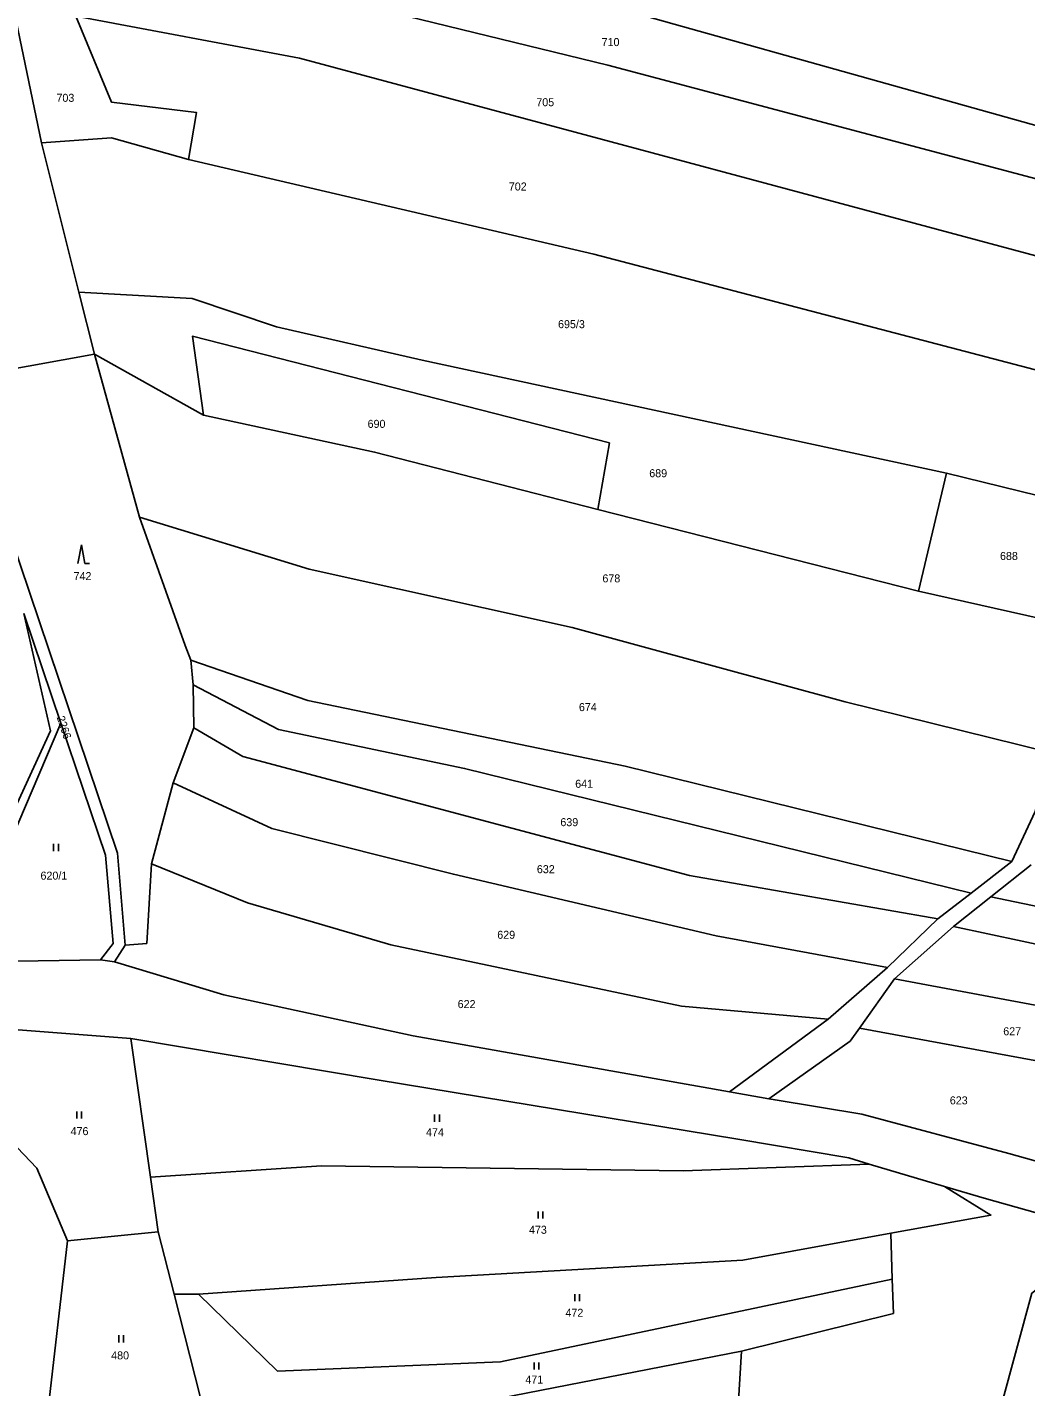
# Model space of a CAD drawing. Extents: x -725728 to -720881, y -1068679 to -1063504.
# Drawn here: x -722501.3 to -722289.2, y -1064708.2 to -1064419.4 of the extents above; entities that cross this region are included whole.
import ezdxf

# ---------------------------------------------------------------- set-up
doc = ezdxf.new("R2010")
doc.units = 0
for name, color, linetype in [('Hranice parcel', 7, 'Continuous'), ('Parcelní čísla', 7, 'Continuous'), ('Značky kultur', 7, 'Continuous')]:
    doc.layers.add(name, color=color, linetype=linetype)

# ---------------------------------------------------------------- blocks, each defined once
blk = doc.blocks.new('3.06_2')
at = {"layer": 'Značky kultur'}
for p, q in [((-0.051, 0), (-0.051, 0.15)), ((0.049, 0), (0.049, 0.15))]:
    blk.add_line(p, q, dxfattribs=at)
blk = doc.blocks.new('3.06_1')
at = {"layer": 'Značky kultur'}
for p, q in [((-0.051, 0), (-0.051, 0.15)), ((0.049, 0), (0.049, 0.15))]:
    blk.add_line(p, q, dxfattribs=at)
blk = doc.blocks.new('3.08_1')
at = {"layer": 'Značky kultur'}
for p, q in [((0, 0.4), (-0.075, 0)), ((0.075, 0), (0, 0.4)), ((0.075, 0), (0.175, 0))]:
    blk.add_line(p, q, dxfattribs=at)

msp = doc.modelspace()

# ---------------------------------------------------------------- linework, layer by layer
at = {"layer": 'Hranice parcel'}
for p, q in [((-722498.29, -1064443.96), (-722503.64, -1064417.98)), ((-722490.33, -1064475.68), (-722498.29, -1064443.96)), ((-722487.03, -1064488.84), (-722490.33, -1064475.68)), ((-722521.13, -1064495), (-722487.03, -1064488.84)), ((-722463.89, -1064501.8), (-722487.03, -1064488.84)), ((-722477.47, -1064523.41), (-722487.03, -1064488.84)), ((-722306.05, -1064514.11), (-722312.04, -1064539.16)), ((-722274.46, -1064521.84), (-722306.05, -1064514.11)), ((-722312.04, -1064539.16), (-722380.12, -1064521.83)), ((-722275.02, -1064547.52), (-722312.04, -1064539.16)), ((-722502.04, -1064543.92), (-722494.19, -1064567.18)), ((-722466.07, -1064559.07), (-722466.59, -1064553.78)), ((-722465.91, -1064568.17), (-722466.07, -1064559.07)), ((-722494.19, -1064567.18), (-722514.39, -1064614.56)), ((-722470.3, -1064579.86), (-722465.91, -1064568.17)), ((-722474.93, -1064597.04), (-722470.3, -1064579.86)), ((-722292.21, -1064596.57), (-722300.87, -1064603.32)), ((-722296.64, -1064604.05), (-722288.13, -1064597.29)), ((-722300.87, -1064603.32), (-722307.89, -1064608.78)), ((-722304.59, -1064610.4), (-722296.64, -1064604.05)), ((-722254.76, -1064612.97), (-722296.64, -1064604.05)), ((-722307.89, -1064608.78), (-722318.59, -1064619.12)), ((-722317.16, -1064621.52), (-722304.59, -1064610.4)), ((-722256.13, -1064620.77), (-722304.59, -1064610.4)), ((-722482.77, -1064617.91), (-722480.5, -1064614.38)), ((-722485.75, -1064617.44), (-722513.18, -1064617.94)), ((-722485.75, -1064617.44), (-722482.77, -1064617.91)), ((-722318.59, -1064619.12), (-722331.23, -1064630.05)), ((-722324.58, -1064631.99), (-722317.16, -1064621.52)), ((-722256.37, -1064632.92), (-722317.16, -1064621.52)), ((-722331.23, -1064630.05), (-722352.2, -1064645.49)), ((-722267.39, -1064642.49), (-722324.58, -1064631.99)), ((-722475.15, -1064663.6), (-722479.32, -1064634.16)), ((-722352.2, -1064645.49), (-722343.81, -1064646.97)), ((-722306.48, -1064665.59), (-722322.48, -1064660.84)), ((-722475.15, -1064663.6), (-722473.51, -1064675.21)), ((-722492.73, -1064677.12), (-722473.51, -1064675.21)), ((-722473.51, -1064675.21), (-722470.11, -1064688.47)), ((-722317.92, -1064675.49), (-722317.6, -1064685.31)), ((-722492.73, -1064677.12), (-722497.82, -1064721.19)), ((-722463.19, -1064715.8), (-722470.11, -1064688.47)), ((-722470.11, -1064688.47), (-722464.91, -1064688.47)), ((-722349.63, -1064700.59), (-722400.79, -1064710.6)), ((-722349.63, -1064700.59), (-722352.45, -1064749.38))]:
    msp.add_line(p, q, dxfattribs=at)
for points in [[(-722251.73, -1064450.13), (-722375.01, -1064415.63), (-722493.86, -1064384.39)], [(-722259.29, -1064458.95), (-722377.98, -1064427.44), (-722497.34, -1064398.25)], [(-722267.88, -1064473.09), (-722443.5, -1064425.95), (-722491.02, -1064416.99)], [(-722491.02, -1064416.99), (-722483.43, -1064435.27), (-722465.34, -1064437.5), (-722467.06, -1064447.49)], [(-722467.06, -1064447.49), (-722483.43, -1064442.88), (-722498.29, -1064443.96)], [(-722273.94, -1064495.64), (-722380.97, -1064467.55), (-722467.06, -1064447.49)], [(-722306.05, -1064514.11), (-722417.43, -1064490.08), (-722448.36, -1064483), (-722466.31, -1064477.01), (-722490.33, -1064475.68)], [(-722463.89, -1064501.8), (-722466.25, -1064485), (-722377.66, -1064507.65), (-722380.12, -1064521.83)], [(-722380.12, -1064521.83), (-722427.55, -1064509.62), (-722463.89, -1064501.8)], [(-722512.18, -1064515.37), (-722509.2, -1064514.82), (-722482.14, -1064594.78), (-722480.5, -1064614.38)], [(-722284.35, -1064573.33), (-722327.61, -1064562.63), (-722385.61, -1064546.87), (-722441.42, -1064534.46), (-722477.47, -1064523.41)], [(-722466.59, -1064553.78), (-722467.74, -1064550.72), (-722477.47, -1064523.41)], [(-722515.73, -1064610.82), (-722496.35, -1064568.81), (-722502.04, -1064543.92)], [(-722292.21, -1064596.57), (-722374.36, -1064576.3), (-722441.75, -1064562.37), (-722466.59, -1064553.78)], [(-722300.87, -1064603.32), (-722408.44, -1064576.81), (-722447.92, -1064568.54), (-722466.07, -1064559.07)], [(-722494.19, -1064567.18), (-722484.73, -1064595.24), (-722483.08, -1064613.99), (-722485.75, -1064617.44)], [(-722307.89, -1064608.78), (-722360.65, -1064599.52), (-722455.53, -1064574.24), (-722465.91, -1064568.17)], [(-722284.35, -1064573.33), (-722287.28, -1064585.95), (-722292.21, -1064596.57)], [(-722318.59, -1064619.12), (-722355, -1064612.34), (-722410.82, -1064599.3), (-722449.34, -1064589.54), (-722470.3, -1064579.86)], [(-722480.5, -1064614.38), (-722475.95, -1064613.99), (-722474.93, -1064597.04)], [(-722331.23, -1064630.05), (-722362.35, -1064627.29), (-722424.09, -1064614.28), (-722454.56, -1064605.34), (-722474.93, -1064597.04)], [(-722352.2, -1064645.49), (-722419.34, -1064633.61), (-722459.57, -1064624.87), (-722482.77, -1064617.91)], [(-722479.32, -1064634.16), (-722509.73, -1064631.86), (-722512.78, -1064631.76)], [(-722512.78, -1064631.76), (-722510.43, -1064650.02), (-722499.25, -1064661.72), (-722492.73, -1064677.12)], [(-722343.81, -1064646.97), (-722326.52, -1064634.72), (-722324.58, -1064631.99)], [(-722479.32, -1064634.16), (-722426.99, -1064642.92), (-722350.38, -1064655.56), (-722326.81, -1064659.55), (-722322.48, -1064660.84)], [(-722282.75, -1064661.41), (-722292.81, -1064658.6), (-722324.03, -1064650.27), (-722342.48, -1064647.21), (-722343.81, -1064646.97)], [(-722322.48, -1064660.84), (-722362.03, -1064662.25), (-722438.83, -1064661.22), (-722475.15, -1064663.6)], [(-722306.48, -1064665.59), (-722296.64, -1064671.68), (-722317.92, -1064675.49)], [(-722271.41, -1064675.59), (-722298.06, -1064668.1), (-722306.48, -1064665.59)], [(-722464.91, -1064688.47), (-722414.45, -1064684.95), (-722349.34, -1064681.28), (-722317.92, -1064675.49)], [(-722307.49, -1064760.09), (-722287.94, -1064688.27), (-722271.41, -1064675.59)], [(-722317.6, -1064685.31), (-722400.78, -1064702.85), (-722448.14, -1064704.83), (-722464.91, -1064688.47)], [(-722317.6, -1064685.31), (-722317.36, -1064692.55), (-722349.63, -1064700.59)]]:
    msp.add_lwpolyline(points, dxfattribs=at)

# ---------------------------------------------------------------- block references
at = {"layer": 'Značky kultur', "xscale": 10, "yscale": 10}
for name, p in [('3.08_1', (-722489.81, -1064533.29)), ('3.06_1', (-722495.2, -1064594.35)), ('3.06_1', (-722490.29, -1064651.19)), ('3.06_1', (-722414.28, -1064651.85)), ('3.06_2', (-722392.32, -1064672.41)), ('3.06_1', (-722384.51, -1064689.96)), ('3.06_1', (-722481.38, -1064698.71)), ('3.06_1', (-722393.17, -1064704.5))]:
    msp.add_blockref(name, p, dxfattribs=at)

# ---------------------------------------------------------------- texts
at = {"layer": 'Parcelní čísla'}
for s, p in [('710', (-722379.33, -1064423.37)), ('703', (-722495.11, -1064435.21)), ('705', (-722393.2, -1064436.15)), ('702', (-722399.04, -1064454.05)), ('695/3', (-722388.58, -1064483.29)), ('690', (-722429.03, -1064504.47)), ('689', (-722369.21, -1064514.95)), ('688', (-722294.72, -1064532.53)), ('742', (-722491.47, -1064536.8)), ('678', (-722379.16, -1064537.29)), ('674', (-722384.15, -1064564.63)), ('641', (-722384.94, -1064580.92)), ('639', (-722388.09, -1064589.07)), ('632', (-722393.08, -1064599.06)), ('620/1', (-722498.5, -1064600.43)), ('629', (-722401.49, -1064612.99)), ('622', (-722409.9, -1064627.71)), ('627', (-722294.03, -1064633.49)), ('623', (-722305.38, -1064648.17)), ('476', (-722492.11, -1064654.7)), ('474', (-722416.61, -1064654.92)), ('473', (-722394.76, -1064675.65)), ('472', (-722387.01, -1064693.28)), ('480', (-722483.49, -1064702.33)), ('471', (-722395.52, -1064707.46))]:
    msp.add_text(s, height=1.7, dxfattribs=at).set_placement(p)
msp.add_text('2266', height=1.7, rotation=288, dxfattribs=at).set_placement((-722495.07, -1064565.95))

doc.saveas('drawing.dxf')
